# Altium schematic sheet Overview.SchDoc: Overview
size A4; Date: Not used; ApprovedBy: Not used; CheckedBy: Not used; Author: Not used; CompanyName: STMicroelectronics; DrawnBy: Not used; Engineer: Not used; Organization: Not used; Address1: Not used; Address2: Not used; Address3: Not used; Address4: Not used; DocumentNumber: 1; Revision: Not used; SheetNumber: 1; SheetTotal: 4
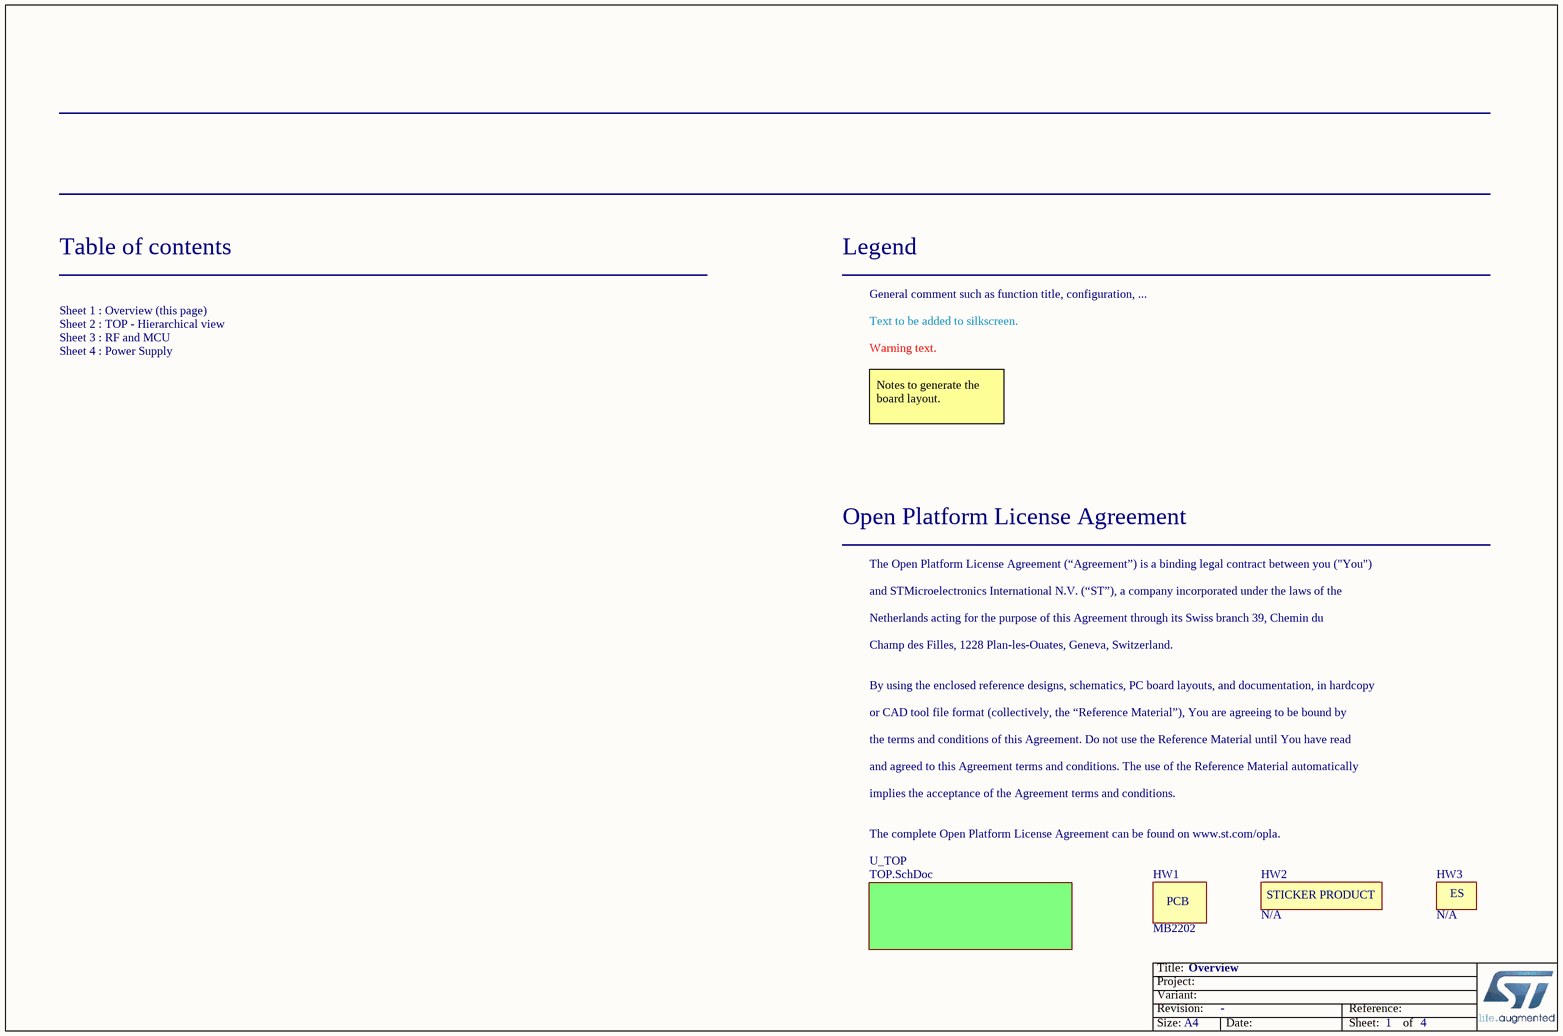
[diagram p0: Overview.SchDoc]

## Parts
HW1  value MB2202  (hidden comment: PCB)
HW2  STICKER_PRODUCT  [STICKER_PRODUCT_25X9]  (value not drawn)  (no BOM)
HW3  STICKER_ES  [STICKER_ES_6X6]  (value not drawn)  (no BOM)

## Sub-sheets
U_TOP = TOP.SchDoc: no entries

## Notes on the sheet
- Table of contents
- Legend
- General comment such as function title, configuration, ...
- Text to be added to silkscreen.
- Warning text.
- Notes to generate the board layout.
- Open Platform License Agreement
- The Open Platform License Agreement (“Agreement”) is a binding legal contract between you ("You")
- and STMicroelectronics International N.V. (“ST”), a company incorporated under the laws of the
- Netherlands acting for the purpose of this Agreement through its Swiss branch 39, Chemin du
- Champ des Filles, 1228 Plan-les-Ouates, Geneva, Switzerland.
- Sheet 1 : Overview (this page)
  Sheet 2 : TOP - Hierarchical view
  Sheet 3 : RF and MCU
  Sheet 4 : Power Supply
- By using the enclosed reference designs, schematics, PC board layouts, and documentation, in hardcopy
- or CAD tool file format (collectively, the “Reference Material”), You are agreeing to be bound by
- the terms and conditions of this Agreement. Do not use the Reference Material until You have read
- and agreed to this Agreement terms and conditions. The use of the Reference Material automatically
- implies the acceptance of the Agreement terms and conditions.
- The complete Open Platform License Agreement can be found on www.st.com/opla.

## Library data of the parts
HW1 = MCD-04953: PCB, MB2202, 41x31 mm, 4L1S, 0.638mm, TG150, VT-47; Part_Preference: Recommended; Manufacturer: SYNERGIE CAD; ShowFields: YES; ID: 7069
HW2 = MCD-00547: Sticker product, 25x9mm; Part_Type: Misc; Part_Preference: Recommended; Component_Country_Of_Origin: Unknown; ShowFields: YES; ID: 3197
HW3 = MCD-00234: Sticker ES, 6x6mm; Part_Type: Misc; Part_Preference: Recommended; Component_Country_Of_Origin: Unknown; ShowFields: YES; ID: 2634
